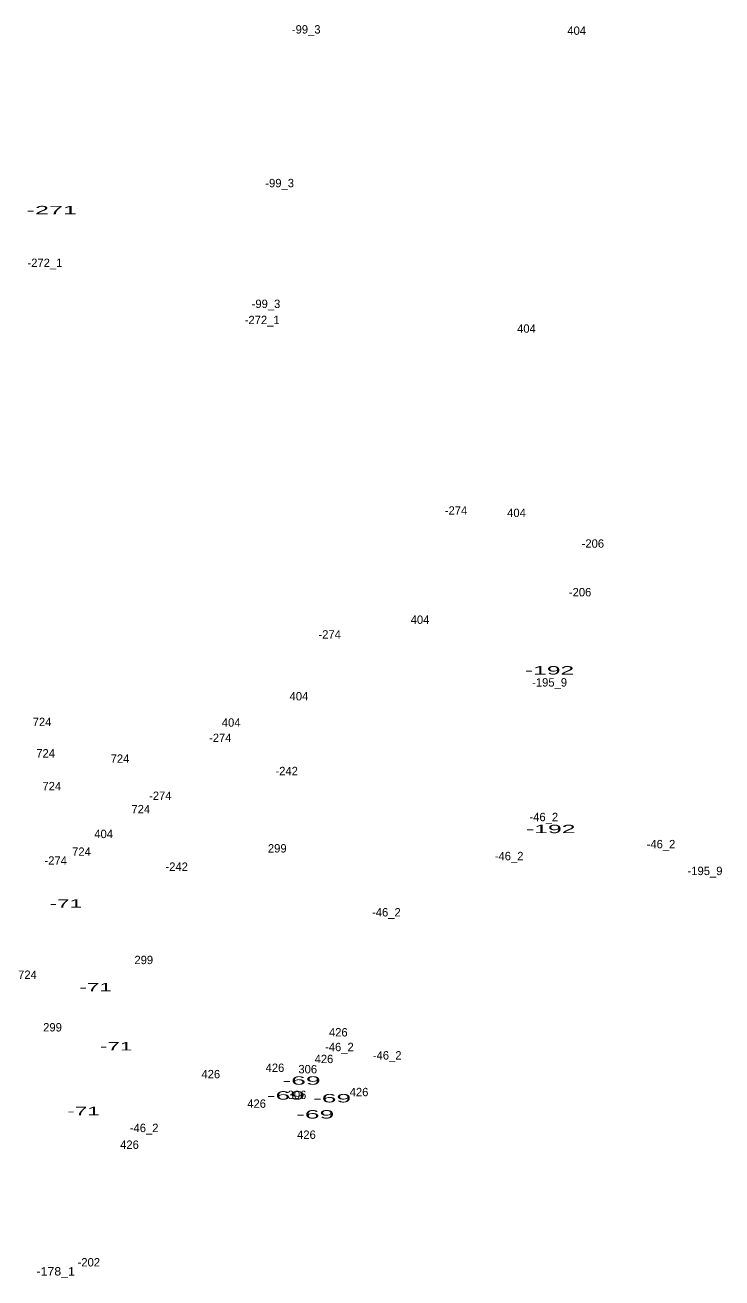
# Model space of a CAD drawing. Extents: x -658595 to -655205, y -1004347 to -1000147.
# Drawn here: x -656415 to -656082, y -1001887 to -1001289 of the extents above; entities that cross this region are included whole.
import ezdxf
from ezdxf.enums import TextEntityAlignment as Align

# ---------------------------------------------------------------- set-up
doc = ezdxf.new("R2010")
doc.units = 0
doc.header["$LTSCALE"] = 1.6
doc.layers.add('24', color=7, linetype='Continuous')

msp = doc.modelspace()

# ---------------------------------------------------------------- texts
at = {"layer": '24'}
for s, p in [('-99_3', (-656280.483, -1001292.68)), ('404', (-656151.4, -1001293.28)), ('-99_3', (-656293.153, -1001366.05)), ('-272_1', (-656405.182, -1001404.11)), ('-99_3', (-656299.683, -1001423.68)), ('-272_1', (-656301.492, -1001431.38)), ('404', (-656175.36, -1001435.5)), ('-274', (-656208.995, -1001522.32)), ('404', (-656180.12, -1001523.46)), ('-206', (-656143.674, -1001538.1)), ('-206', (-656149.764, -1001561.32)), ('404', (-656226.15, -1001574.45)), ('-274', (-656269.285, -1001581.48)), ('-195_9', (-656164.317, -1001604.38)), ('404', (-656283.96, -1001610.97)), ('724', (-656406.537, -1001623.24)), ('404', (-656316.29, -1001623.53)), ('-274', (-656321.505, -1001630.84)), ('724', (-656404.847, -1001638.25)), ('724', (-656369.347, -1001640.78)), ('-242', (-656289.799, -1001646.69)), ('724', (-656401.887, -1001653.89)), ('-274', (-656350.125, -1001658.5)), ('724', (-656359.417, -1001664.88)), ('-46_2', (-656167.082, -1001668.64)), ('404', (-656377.15, -1001676.71)), ('-46_2', (-656111.172, -1001681.58)), ('724', (-656387.727, -1001685.17)), ('299', (-656294.288, -1001683.59)), ('-46_2', (-656183.632, -1001687.28)), ('-274', (-656400.045, -1001689.42)), ('-242', (-656342.289, -1001692.35)), ('-195_9', (-656090.147, -1001694.37)), ('-46_2', (-656242.212, -1001714.11)), ('299', (-656358.008, -1001736.86)), ('724', (-656413.507, -1001743.93)), ('299', (-656401.558, -1001769.01)), ('426', (-656265.157, -1001771.4)), ('-46_2', (-656264.632, -1001778.42)), ('426', (-656272.007, -1001784.11)), ('-46_2', (-656241.832, -1001782.41)), ('426', (-656295.397, -1001788.33)), ('306', (-656279.747, -1001788.99)), ('426', (-656326.017, -1001791.37)), ('306', (-656284.877, -1001801.26)), ('426', (-656255.267, -1001799.93)), ('426', (-656304.147, -1001805.45)), ('-46_2', (-656357.822, -1001817.04)), ('426', (-656280.377, -1001820.29)), ('426', (-656364.817, -1001825.05)), ('-202', (-656384.229, -1001881.17))]:
    msp.add_text(s, height=4, dxfattribs=at).set_placement(p, align=Align.CENTER)
for s, width, p in [('-271', 2.25, (-656401.905, -1001378.95)), ('-192', 2.2, (-656164.345, -1001598.62)), ('-192', 2.2, (-656163.775, -1001674.34)), ('-71', 2, (-656395.195, -1001709.91)), ('-71', 2, (-656380.985, -1001749.86)), ('-71', 2, (-656371.195, -1001778.06)), ('-69', 2.35, (-656282.733, -1001794.42)), ('-69', 2.35, (-656290.223, -1001801.53)), ('-69', 2.35, (-656268.143, -1001802.87)), ('-71', 2, (-656386.745, -1001808.98)), ('-69', 2.35, (-656276.203, -1001810.56)), ('-178_1', 1.1, (-656400.041, -1001885.5))]:
    msp.add_text(s, height=4, dxfattribs=dict(at, width=width)).set_placement(p, align=Align.CENTER)

doc.saveas('drawing.dxf')
